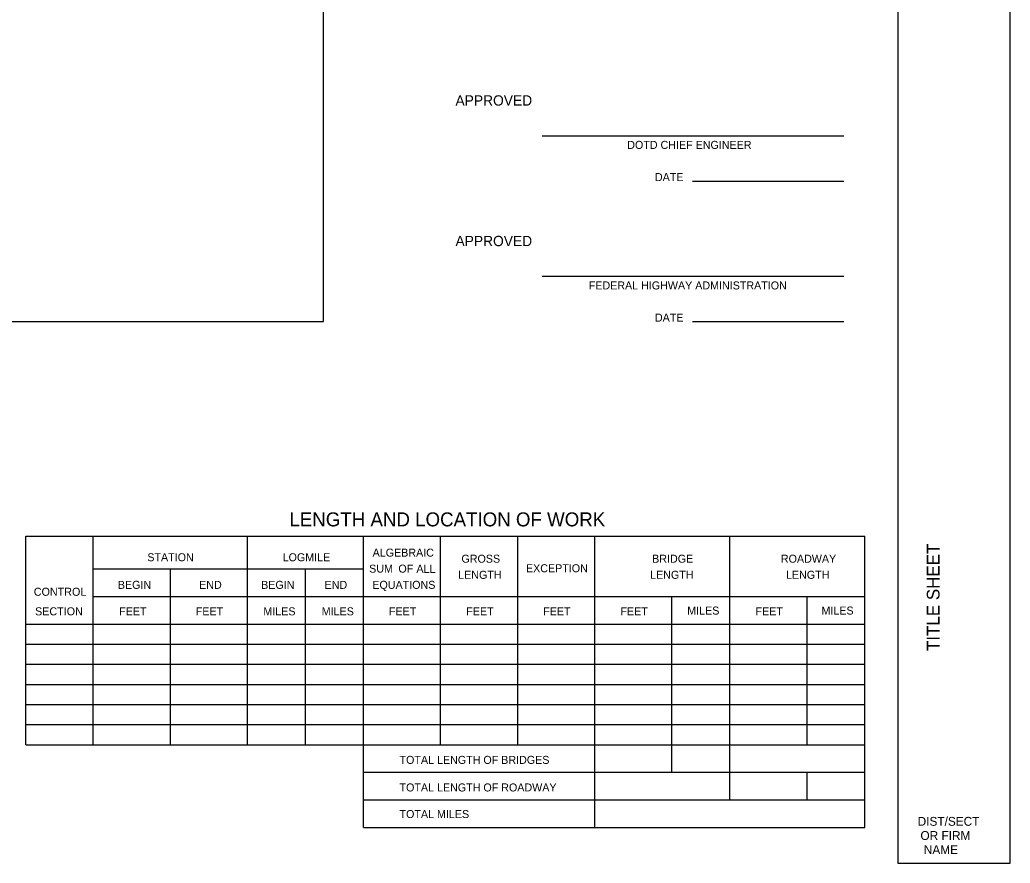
# Model space of a CAD drawing. Extents: x 0.23 to 2.82, y 0.04 to 1.79.
# Drawn here: x 1.79 to 2.817, y 0.042 to 0.917 of the extents above; entities that cross this region are included whole.
import ezdxf

# ---------------------------------------------------------------- set-up
doc = ezdxf.new("R2010")
doc.units = 0
for name, color, linetype in [('Annotation', 7, 'Continuous'), ('Layout Map Info', 7, 'Continuous'), ('Standard Info', 7, 'Continuous')]:
    doc.layers.add(name, color=color, linetype=linetype)

msp = doc.modelspace()

# ---------------------------------------------------------------- linework, layer by layer
at = {"layer": 'Annotation'}
msp.add_lwpolyline([(2.7, 0.0417), (2.8167, 0.0417), (2.8167, 1.7916), (2.7, 1.7916)], close=True, dxfattribs=at)
at = {"layer": 'Layout Map Info'}
msp.add_lwpolyline([(0.9038, 0.6035), (2.1045, 0.6035), (2.1045, 1.1298), (0.9038, 1.1298)], close=True, dxfattribs=at)
at = {"layer": 'Standard Info'}
for p, q in [((2.3314, 0.7963), (2.6442, 0.7963)), ((2.4874, 0.7493), (2.6442, 0.7493)), ((2.3314, 0.6505), (2.6442, 0.6505)), ((2.4874, 0.6035), (2.6442, 0.6035)), ((1.796, 0.3809), (2.666, 0.3809)), ((1.796, 0.1646), (1.796, 0.3809)), ((1.866, 0.1646), (1.866, 0.3809)), ((2.026, 0.1646), (2.026, 0.3809)), ((2.146, 0.0787), (2.146, 0.3809)), ((2.226, 0.1646), (2.226, 0.3809)), ((2.306, 0.1646), (2.306, 0.3809)), ((2.386, 0.0787), (2.386, 0.3809)), ((2.526, 0.1075), (2.526, 0.3809)), ((2.666, 0.0787), (2.666, 0.3809)), ((1.866, 0.3471), (2.146, 0.3471)), ((1.946, 0.1646), (1.946, 0.3471)), ((2.086, 0.1646), (2.086, 0.3471)), ((1.866, 0.3184), (2.666, 0.3184)), ((2.466, 0.136), (2.466, 0.3184)), ((2.606, 0.1646), (2.606, 0.3184)), ((1.796, 0.2896), (2.666, 0.2896)), ((1.796, 0.2688), (2.666, 0.2688)), ((1.796, 0.248), (2.666, 0.248)), ((1.796, 0.2271), (2.666, 0.2271)), ((1.796, 0.2063), (2.666, 0.2063)), ((1.796, 0.1855), (2.666, 0.1855)), ((1.796, 0.1646), (2.666, 0.1646)), ((2.146, 0.136), (2.666, 0.136)), ((2.606, 0.1075), (2.606, 0.136)), ((2.146, 0.1075), (2.666, 0.1075)), ((2.146, 0.0787), (2.666, 0.0787))]:
    msp.add_line(p, q, dxfattribs=at)

# ---------------------------------------------------------------- texts
at = {"layer": 'Annotation'}
msp.add_text('           TITLE SHEET           ', height=0.013166, rotation=90, dxfattribs=at).set_placement((2.7434, 0.2079))
for s, p in [(' DIST/SECT', (2.7173, 0.0805)), ('  OR FIRM ', (2.7168, 0.0658)), ('   NAME   ', (2.7169, 0.0511))]:
    msp.add_text(s, height=0.00917, dxfattribs=at).set_placement(p)
at = {"layer": 'Standard Info'}
for s, height, p in [('APPROVED', 0.0107, (2.2415, 0.8276)), ('DOTD CHIEF ENGINEER', 0.0083, (2.4196, 0.7827)), ('DATE', 0.0083, (2.4483, 0.7493)), ('APPROVED', 0.0107, (2.2415, 0.6818)), ('FEDERAL HIGHWAY ADMINISTRATION', 0.0083, (2.3797, 0.6369)), ('DATE', 0.0083, (2.4483, 0.6035)), ('LENGTH AND LOCATION OF WORK', 0.0145, (2.0693, 0.3911)), ('STATION', 0.0083, (1.922, 0.3549)), ('LOGMILE', 0.0083, (2.0623, 0.3549)), ('ALGEBRAIC', 0.0083, (2.1556, 0.3597)), ('GROSS', 0.0083, (2.2477, 0.3534)), ('BRIDGE', 0.0083, (2.4454, 0.3534)), ('ROADWAY', 0.0083, (2.5789, 0.3534)), ('SUM', 0.0083, (2.152, 0.3431)), ('OF', 0.00833, (2.1823, 0.3431)), ('ALL', 0.00833, (2.201, 0.3429)), ('EXCEPTION', 0.0083, (2.3146, 0.3435)), ('LENGTH', 0.0083, (2.2443, 0.3367)), ('LENGTH', 0.0083, (2.4433, 0.3367)), ('LENGTH', 0.0083, (2.5842, 0.3367)), ('BEGIN', 0.0083, (1.8914, 0.3263)), ('END', 0.0083, (1.9757, 0.3263)), ('BEGIN', 0.0083, (2.04, 0.3263)), ('END', 0.0083, (2.1058, 0.3263)), ('EQUATIONS', 0.0083, (2.1553, 0.3263)), ('CONTROL', 0.00833, (1.8043, 0.3191)), ('SECTION', 0.00833, (1.8056, 0.2988)), ('FEET', 0.0083, (1.8928, 0.2988)), ('FEET', 0.0083, (1.9722, 0.2988)), ('MILES', 0.0083, (2.0423, 0.2988)), ('MILES', 0.0083, (2.1028, 0.2988)), ('FEET', 0.0083, (2.1725, 0.2988)), ('FEET', 0.0083, (2.2527, 0.2988)), ('FEET', 0.0083, (2.3325, 0.2988)), ('FEET', 0.0083, (2.4125, 0.2988)), ('MILES', 0.0083, (2.4818, 0.2996)), ('FEET', 0.0083, (2.5526, 0.2988)), ('MILES', 0.0083, (2.621, 0.2996)), ('TOTAL LENGTH OF BRIDGES', 0.0083, (2.1835, 0.1447)), ('TOTAL LENGTH OF ROADWAY', 0.0083, (2.1835, 0.1161)), ('TOTAL MILES', 0.0083, (2.1835, 0.0885))]:
    msp.add_text(s, height=height, dxfattribs=at).set_placement(p)

doc.saveas('drawing.dxf')
